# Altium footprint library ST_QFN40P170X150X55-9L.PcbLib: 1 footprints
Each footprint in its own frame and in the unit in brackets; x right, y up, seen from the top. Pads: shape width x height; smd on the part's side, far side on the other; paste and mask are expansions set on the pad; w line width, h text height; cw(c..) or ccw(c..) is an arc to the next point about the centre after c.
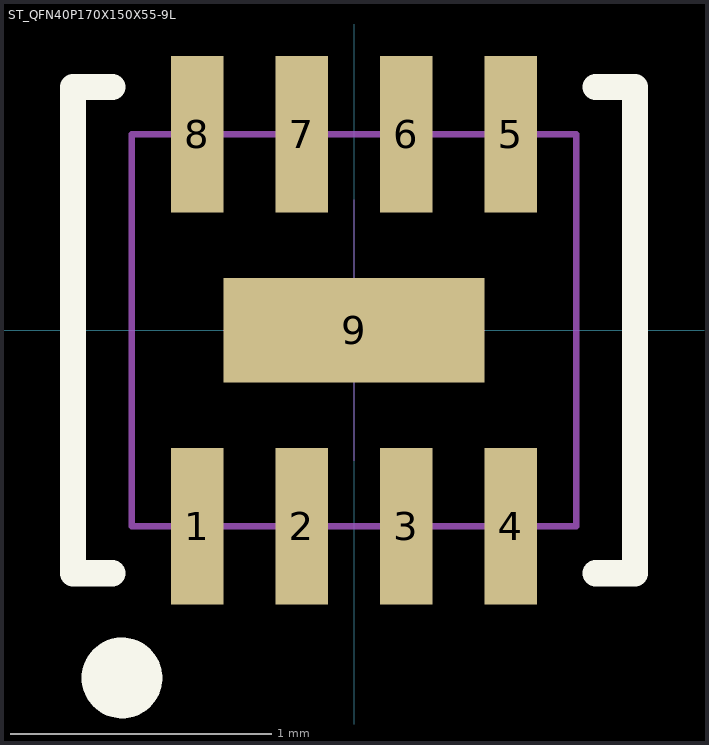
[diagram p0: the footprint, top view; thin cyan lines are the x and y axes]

## ST_QFN40P170X150X55-9L [mm] "ST_QFN40P170X150X55-9L"
pads (9):
  rect 0.2x0.6 smd paste-20 mask+0.03: 1(-0.6,-0.75) 2(-0.2,-0.75) 3(0.2,-0.75) 4(0.6,-0.75) 5(0.6,0.75) 6(0.2,0.75) 7(-0.2,0.75) 8(-0.6,0.75)
  rect 1x0.4 smd paste-20 mask+0.03: 9(0,0)
Top Overlay:
  circle w0.2: c-0.888,-1.33 r0.054
  lines w0.1: -0.925,-0.93 -1.075,-0.93 -1.075,0.93 -0.925,0.93 ; 0.925,-0.93 1.075,-0.93 1.075,0.93 0.925,0.93
Top Paste:
  rectangle: -0.695,-1.035 -0.505,-0.465
  rectangle: -0.295,-1.035 -0.105,-0.465
  rectangle: 0.105,-1.035 0.295,-0.465
  rectangle: 0.505,-1.035 0.695,-0.465
  rectangle: 0.505,0.465 0.695,1.035
  rectangle: 0.105,0.465 0.295,1.035
  rectangle: -0.295,0.465 -0.105,1.035
  rectangle: -0.695,0.465 -0.505,1.035
  rectangle: -0.34,-0.15 0.34,0.15
Mechanical 5:
  text "8" at -0.61,1.13 h0.05
  text "1" at -0.64,-1.19 h0.05
  text "2" at -0.24,-1.21 h0.05
  text "7" at -0.225,1.15 h0.05
  text "9" at -0.69,0.005 h0.05
  text "4" at 0.55,-1.21 h0.05
  text "5" at 0.565,1.16 h0.05
  text "3" at 0.165,-1.21 h0.05
  text "6" at 0.165,1.15 h0.05
Mechanical 6:
  lines w0.025: -0.85,-0.75 -0.85,0.75 0.85,0.75 0.85,-0.75 -0.85,-0.75
Mechanical 7:
  lines w0.025: -0.85,-0.75 0.85,-0.75 0.85,0.75 -0.85,0.75 -0.85,-0.75
Mechanical 15:
  lines w0.001: -0.5,0 0.5,0 ; 0,-0.5 0,0.5
3D body: height 0.6, standoff 0, extent -0.85,-0.75 0.85,0.75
